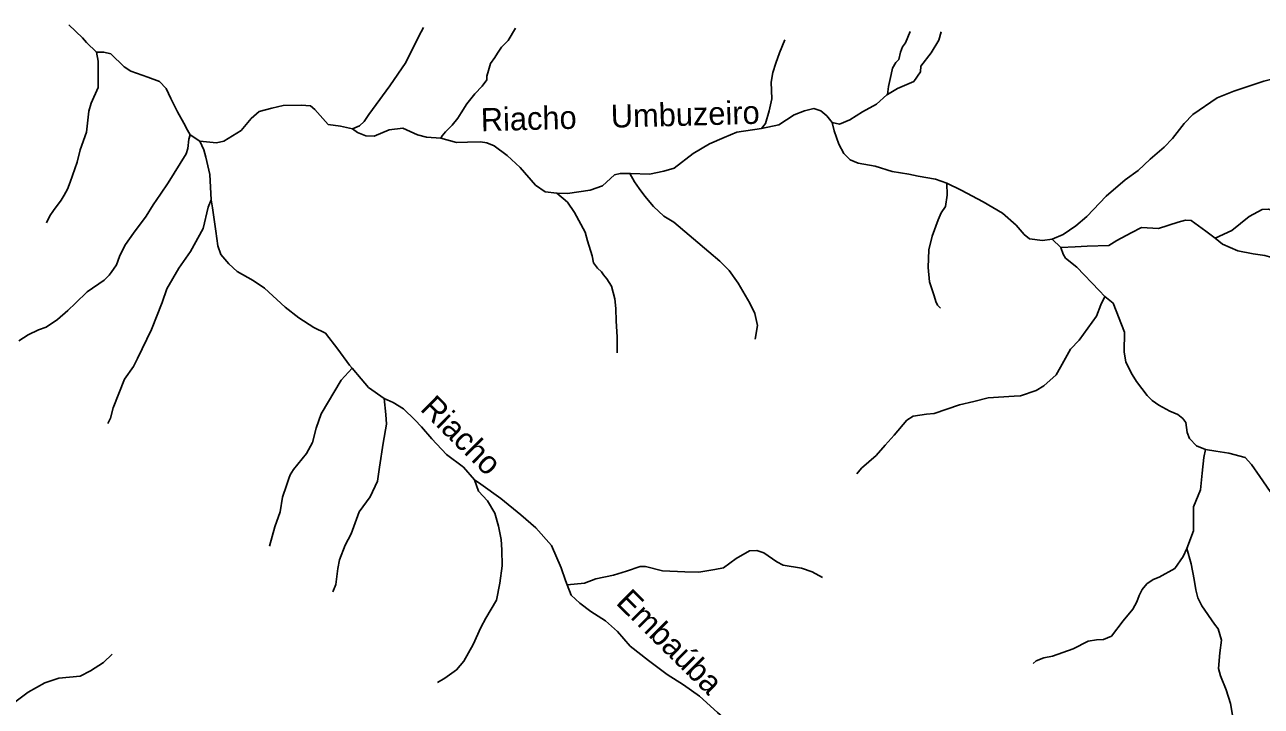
# Model space of a CAD drawing. Extents: x 717.8 to 772.7, y 8672.2 to 8728.
# Drawn here: x 745.36 to 756.1, y 8721.84 to 8727.76 of the extents above; entities that cross this region are included whole.
import ezdxf
from ezdxf.enums import TextEntityAlignment as Align

# ---------------------------------------------------------------- set-up
doc = ezdxf.new("R2010")
doc.units = 0
doc.header["$LTSCALE"] = 0.08
doc.linetypes.add('LONG_DASHED', pattern=[7.5, 6, -1.5])
doc.layers.add('61', color=7, linetype='Continuous')
doc.layers.add('9', color=7, linetype='LONG_DASHED', lineweight=25)

msp = doc.modelspace()

# ---------------------------------------------------------------- linework, layer by layer
at = {"layer": '9'}
for p, q in [((749.6275, 8727.726), (749.5623, 8727.6187)), ((746.8837, 8726.7438), (746.8014, 8726.7992))]:
    msp.add_line(p, q, dxfattribs=at)
for points in [[(745.7481, 8727.7567), (745.8668, 8727.6439), (745.9006, 8727.6014), (745.9877, 8727.5191)], [(748.2115, 8726.8523), (748.2708, 8726.8773), (748.3109, 8726.9155), (748.353, 8726.9771), (748.3841, 8727.0203), (748.5349, 8727.2265), (748.674, 8727.428), (748.7862, 8727.657), (748.8274, 8727.7327)], [(753.054, 8727.6982), (753.0136, 8727.5995), (752.9888, 8727.5648), (752.9694, 8727.5189), (752.9563, 8727.4546), (752.9305, 8727.4285), (752.9006, 8727.38), (752.888, 8727.3241), (752.8649, 8727.2194), (752.856, 8727.1491)], [(753.3221, 8727.696), (753.302, 8727.6217), (753.2353, 8727.5134), (753.1474, 8727.3962), (753.145, 8727.3471), (753.0863, 8727.2637), (752.943, 8727.2015), (752.856, 8727.1491)], [(749.5623, 8727.6187), (749.5033, 8727.5604), (749.4686, 8727.5108), (749.4454, 8727.4731), (749.4092, 8727.4186), (749.3912, 8727.3604), (749.3768, 8727.3095), (749.3779, 8727.2777), (749.3357, 8727.222), (749.2726, 8727.1573)], [(751.7637, 8726.8544), (751.7976, 8726.8975), (751.8307, 8727.0087), (751.8517, 8727.1129), (751.8467, 8727.2581), (751.8611, 8727.3417), (751.8862, 8727.4218), (751.9187, 8727.5127), (751.9652, 8727.6246)], [(745.5533, 8726.0352), (745.5817, 8726.0965), (745.6124, 8726.1432), (745.679, 8726.233), (745.7048, 8726.2754), (745.7343, 8726.3292), (745.7595, 8726.3877), (745.8181, 8726.5639), (745.8465, 8726.6701), (745.8996, 8726.8245), (745.9211, 8727.0067), (745.941, 8727.076), (746.0014, 8727.2108), (746.001, 8727.4398), (745.9877, 8727.5191)], [(746.8014, 8726.7992), (746.777, 8726.8397), (746.7445, 8726.9002), (746.6911, 8726.9991), (746.6312, 8727.1168), (746.5915, 8727.203), (746.5329, 8727.2635), (746.4322, 8727.302), (746.2862, 8727.353), (746.2262, 8727.3915), (746.1129, 8727.5028), (746.0497, 8727.5171), (745.9877, 8727.5191)], [(756.4406, 8727.3316), (756.3851, 8727.3307), (756.3369, 8727.3185), (756.1262, 8727.2669), (755.8644, 8727.1781), (755.7217, 8727.1203), (755.5081, 8726.9775), (755.4349, 8726.8991), (755.3341, 8726.7685), (755.2591, 8726.6938), (755.139, 8726.5879), (755.0338, 8726.4895), (754.923, 8726.4081), (754.7553, 8726.2679), (754.5882, 8726.0904), (754.4922, 8726.0084), (754.3818, 8725.9344), (754.2874, 8725.8947)], [(749.2726, 8727.1573), (749.2044, 8727.0683), (749.1541, 8726.991), (749.1258, 8726.9452), (749.0756, 8726.884), (749.017, 8726.8263), (748.9884, 8726.7917), (748.9771, 8726.7714)], [(752.856, 8727.1491), (752.8516, 8727.1464), (752.7618, 8727.0675), (752.6413, 8726.9996), (752.5314, 8726.9293), (752.4407, 8726.8922), (752.3758, 8726.9078)], [(748.2115, 8726.8523), (748.1062, 8726.8739), (747.9983, 8726.8905), (747.8846, 8727.0199), (747.8467, 8727.0528), (747.7644, 8727.0576), (747.6097, 8727.0563), (747.5101, 8727.032), (747.399, 8727.0016), (747.3301, 8726.9427), (747.2435, 8726.8366), (747.0929, 8726.7441), (747.0283, 8726.7296), (746.8837, 8726.7438)], [(752.3758, 8726.9078), (752.3313, 8726.9664), (752.2777, 8727.0077), (752.2179, 8727.029), (752.1376, 8727.0097), (752.046, 8726.973), (751.9142, 8726.8871), (751.7637, 8726.8544)], [(748.2115, 8726.8523), (748.2533, 8726.8202), (748.325, 8726.7901), (748.3997, 8726.7891), (748.5295, 8726.8442), (748.6464, 8726.8589), (748.7745, 8726.8009), (748.8545, 8726.7797), (748.9771, 8726.7714)], [(751.7637, 8726.8544), (751.5494, 8726.8219), (751.4373, 8726.7763), (751.3102, 8726.7206), (751.1705, 8726.6376), (751.0031, 8726.5112), (750.9142, 8726.4833), (750.7911, 8726.4594), (750.6249, 8726.465), (750.6181, 8726.465)], [(753.3735, 8726.3787), (753.2753, 8726.4137), (753.1234, 8726.4419), (753.0423, 8726.4577), (752.8966, 8726.4817), (752.7488, 8726.5271), (752.6016, 8726.5526), (752.5322, 8726.5821), (752.4772, 8726.6378), (752.436, 8726.7183), (752.3947, 8726.8357), (752.3758, 8726.9078)], [(745.3121, 8725.01), (745.3933, 8725.0627), (745.482, 8725.1048), (745.5492, 8725.1303), (745.6485, 8725.196), (745.7385, 8725.275), (745.804, 8725.3374), (745.9068, 8725.4362), (746.0537, 8725.5365), (746.0978, 8725.5807), (746.1141, 8725.6049), (746.16, 8725.6703), (746.1861, 8725.7435), (746.2136, 8725.7972), (746.2397, 8725.8464), (746.3083, 8725.9448), (746.4183, 8726.0939), (746.4801, 8726.1914), (746.5441, 8726.2831), (746.6082, 8726.384), (746.7661, 8726.6344), (746.7803, 8726.6811), (746.7885, 8726.7627), (746.8014, 8726.7992)], [(746.9835, 8726.2367), (746.9718, 8726.4563), (746.937, 8726.6053), (746.9205, 8726.6705), (746.8837, 8726.7438)], [(749.984, 8726.2946), (749.8833, 8726.305), (749.8005, 8726.3632), (749.6671, 8726.5156), (749.5533, 8726.6214), (749.442, 8726.7043), (749.3773, 8726.7314), (749.3222, 8726.7404), (749.2093, 8726.7374), (749.1126, 8726.7344), (748.9771, 8726.7714)], [(750.6181, 8726.465), (750.5351, 8726.4655), (750.4865, 8726.4524), (750.3827, 8726.3581), (750.2749, 8726.3202), (750.0783, 8726.2906), (749.984, 8726.2946)], [(751.7079, 8725.0243), (751.7268, 8725.1444), (751.7036, 8725.2491), (751.6621, 8725.337), (751.5609, 8725.5113), (751.4822, 8725.6221), (751.3997, 8725.7038), (751.3069, 8725.7839), (751.001, 8726.0417), (750.9158, 8726.0929), (750.8258, 8726.1761), (750.7506, 8726.2684), (750.6994, 8726.3326), (750.6605, 8726.3907), (750.6181, 8726.465)], [(753.3182, 8725.2935), (753.2907, 8725.3199), (753.277, 8725.3508), (753.2632, 8725.4024), (753.222, 8725.5227), (753.2106, 8725.6484), (753.216, 8725.8007), (753.2448, 8725.9204), (753.2961, 8726.0619), (753.3224, 8726.1224), (753.3608, 8726.1785), (753.3744, 8726.2753), (753.3735, 8726.3787)], [(754.2874, 8725.8947), (754.2048, 8725.8827), (754.0918, 8725.8955), (754.0448, 8725.9332), (753.9755, 8726.0161), (753.8564, 8726.1193), (753.6878, 8726.2176), (753.4984, 8726.3192), (753.3735, 8726.3787)], [(750.5086, 8724.905), (750.5094, 8725.0449), (750.4998, 8725.1808), (750.4971, 8725.2914), (750.4878, 8725.3739), (750.46, 8725.4839), (750.4208, 8725.5502), (750.392, 8725.583), (750.3736, 8725.6093), (750.3377, 8725.6421), (750.3049, 8725.6877), (750.2922, 8725.7477), (750.253, 8725.878), (750.2322, 8725.9531), (750.1395, 8726.1266), (750.0793, 8726.2148), (749.984, 8726.2946)], [(756.9762, 8726.3485), (756.8833, 8726.2784), (756.6995, 8726.2187), (756.6152, 8726.1826), (756.4684, 8726.1324), (756.2621, 8726.1268), (756.1651, 8726.153), (756.1115, 8726.1515), (755.9995, 8726.0901), (755.8472, 8725.968), (755.7044, 8725.9013)], [(746.0853, 8724.2932), (746.1095, 8724.3382), (746.1309, 8724.4271), (746.2307, 8724.6758), (746.3078, 8724.7884), (746.3437, 8724.8554), (746.4645, 8725.1088), (746.5581, 8725.3437), (746.5967, 8725.4616), (746.7022, 8725.6422), (746.8029, 8725.787), (746.9125, 8725.9848), (746.9581, 8726.1719), (746.9835, 8726.2367)], [(748.2083, 8724.7728), (748.1853, 8724.7984), (748.0831, 8724.9377), (747.9755, 8725.0773), (747.8749, 8725.1251), (747.7438, 8725.211), (747.6253, 8725.3014), (747.4473, 8725.4675), (747.3464, 8725.534), (747.2097, 8725.6112), (747.1351, 8725.6795), (747.0678, 8725.7597), (747.0421, 8725.8344), (747.0235, 8725.9627), (746.9957, 8726.1644), (746.9835, 8726.2367)], [(755.7044, 8725.9013), (755.6211, 8725.9632), (755.495, 8726.0569), (755.4457, 8726.0574), (755.381, 8726.0414), (755.2114, 8725.9848), (755.0649, 8725.9937), (754.9735, 8725.9478), (754.8482, 8725.8818), (754.7783, 8725.8382), (754.5905, 8725.8314), (754.4887, 8725.828), (754.3639, 8725.8203), (754.2874, 8725.8947)], [(756.6542, 8725.4873), (756.4013, 8725.6568), (756.3419, 8725.6824), (756.2368, 8725.7241), (756.1352, 8725.7512), (756.0337, 8725.7675), (755.9011, 8725.7913), (755.766, 8725.851), (755.7044, 8725.9013)], [(754.7442, 8725.3956), (754.6945, 8725.4471), (754.502, 8725.6507), (754.4021, 8725.7274), (754.3821, 8725.7642), (754.3639, 8725.8203)], [(752.5906, 8723.8542), (752.6318, 8723.9047), (752.7584, 8724.015), (752.8376, 8724.1036), (752.9145, 8724.1914), (753.0255, 8724.322), (753.0791, 8724.3546), (753.1956, 8724.3725), (753.264, 8724.3779), (753.4829, 8724.4549), (753.6082, 8724.483), (753.731, 8724.5155), (753.957, 8724.5292), (754.0138, 8724.5316), (754.1494, 8724.5783), (754.2139, 8724.6193), (754.3235, 8724.7149), (754.3599, 8724.7807), (754.4481, 8724.939), (754.5231, 8725.0158), (754.5589, 8725.0693), (754.6731, 8725.2247), (754.7114, 8725.3227), (754.7442, 8725.3956)], [(755.6195, 8724.0675), (755.5409, 8724.098), (755.4803, 8724.1624), (755.4611, 8724.2149), (755.448, 8724.3019), (755.4235, 8724.3356), (755.3788, 8724.3708), (755.3094, 8724.3986), (755.2139, 8724.4515), (755.1564, 8724.4911), (755.1121, 8724.5354), (755.0189, 8724.6558), (754.9824, 8724.7178), (754.9288, 8724.8258), (754.9125, 8724.9144), (754.915, 8725.0866), (754.8174, 8725.3385), (754.7442, 8725.3956)], [(747.4903, 8723.226), (747.5364, 8723.3936), (747.5818, 8723.5247), (747.603, 8723.6528), (747.638, 8723.7535), (747.6567, 8723.8134), (747.6696, 8723.8452), (747.6977, 8723.893), (747.8121, 8724.0316), (747.8621, 8724.1271), (747.8945, 8724.2517), (747.9373, 8724.3757), (748.1124, 8724.6698), (748.2083, 8724.7728)], [(748.4867, 8724.5098), (748.3494, 8724.604), (748.2854, 8724.6787), (748.2083, 8724.7728)], [(748.0405, 8722.8281), (748.0657, 8722.894), (748.0833, 8723.0333), (748.0987, 8723.1069), (748.148, 8723.2353), (748.1996, 8723.3341), (748.2698, 8723.524), (748.3641, 8723.6558), (748.4278, 8723.7919), (748.4453, 8723.9126), (748.476, 8724.12), (748.5045, 8724.2868), (748.5012, 8724.3692), (748.4867, 8724.5098)], [(749.2694, 8723.8025), (749.1759, 8723.9115), (749.0267, 8724.0224), (748.8994, 8724.1574), (748.8094, 8724.2627), (748.7524, 8724.3253), (748.6548, 8724.4207), (748.5637, 8724.4734), (748.4867, 8724.5098)], [(755.4579, 8723.2047), (755.5157, 8723.3582), (755.5164, 8723.5694), (755.5749, 8723.7163), (755.5908, 8723.8594), (755.6061, 8723.9954), (755.6195, 8724.0675)], [(756.3163, 8723.5385), (756.1824, 8723.7026), (756.09, 8723.8301), (756.0192, 8723.9359), (755.9633, 8723.9978), (755.8208, 8724.0337), (755.7087, 8724.0529), (755.6195, 8724.0675)], [(748.9477, 8722.0432), (749.012, 8722.0798), (749.1129, 8722.1529), (749.1772, 8722.2261), (749.2598, 8722.3725), (749.3241, 8722.519), (749.37, 8722.6013), (749.4615, 8722.7577), (749.4893, 8722.9034), (749.5115, 8723.0549), (749.5073, 8723.1955), (749.503, 8723.2829), (749.4796, 8723.399), (749.4455, 8723.513), (749.3825, 8723.6192), (749.304, 8723.7043), (749.2694, 8723.8025)], [(750.0747, 8722.8912), (750.061, 8722.9281), (750.0216, 8723.0379), (749.9402, 8723.2318), (749.8033, 8723.3862), (749.6737, 8723.4976), (749.4977, 8723.6409), (749.326, 8723.7652), (749.2694, 8723.8025)], [(752.2923, 8722.9529), (752.2039, 8723.004), (752.1097, 8723.0345), (751.9515, 8723.062), (751.8959, 8723.0904), (751.7827, 8723.1687), (751.7217, 8723.1878), (751.6593, 8723.1849), (751.5437, 8723.1181), (751.4321, 8723.0366), (751.358, 8723.0231), (751.2184, 8723.0001), (751.0958, 8723.0033), (750.9031, 8723.0126), (750.7563, 8723.0492), (750.7103, 8723.0492), (750.5903, 8723.0081), (750.4761, 8722.9739), (750.323, 8722.9421), (750.2252, 8722.9056), (750.0747, 8722.8912)], [(754.1218, 8722.2079), (754.15, 8722.2312), (754.2161, 8722.2548), (754.2904, 8722.27), (754.4702, 8722.3348), (754.5998, 8722.4004), (754.6728, 8722.4133), (754.7325, 8722.4167), (754.8041, 8722.4457), (754.9046, 8722.5761), (754.9881, 8722.6784), (755.0222, 8722.7432), (755.0418, 8722.7987), (755.0699, 8722.8507), (755.1108, 8722.9001), (755.1661, 8722.9354), (755.2172, 8722.9565), (755.3527, 8723.0331), (755.4255, 8723.1365), (755.4579, 8723.2047)], [(755.9085, 8721.4291), (755.8808, 8721.562), (755.8533, 8721.6662), (755.8538, 8721.7586), (755.8357, 8721.8593), (755.7991, 8721.9783), (755.7491, 8722.101), (755.7315, 8722.1641), (755.7427, 8722.3001), (755.7579, 8722.4088), (755.7283, 8722.5079), (755.6979, 8722.5487), (755.5864, 8722.7074), (755.5532, 8722.7782), (755.5344, 8722.8464), (755.5216, 8722.9368), (755.4944, 8723.0723), (755.4579, 8723.2047)], [(751.9137, 8721.3301), (751.808, 8721.4281), (751.6443, 8721.5671), (751.5113, 8721.6684), (751.3817, 8721.7804), (751.225, 8721.9241), (751.0848, 8722.0219), (750.9435, 8722.1126), (750.7822, 8722.2316), (750.6232, 8722.3565), (750.5133, 8722.4849), (750.4066, 8722.5769), (750.2794, 8722.6594), (750.184, 8722.7301), (750.1089, 8722.8014), (750.0747, 8722.8912)], [(746.124, 8722.2868), (746.0491, 8722.2161), (745.9355, 8722.1432), (745.8442, 8722.0964), (745.6584, 8722.0798), (745.5382, 8722.0381), (745.3923, 8721.9573), (745.278, 8721.8707), (745.2138, 8721.8353), (745.1248, 8721.7469), (745.0681, 8721.6093), (745.0438, 8721.5121), (744.979, 8721.3745), (744.8899, 8721.245), (744.7716, 8721.1422), (744.6195, 8721.0435)]]:
    msp.add_lwpolyline(points, dxfattribs=at)

# ---------------------------------------------------------------- texts
at = {"layer": '61'}
for s, rotation, p in [('Riacho    Umbuzeiro', 1.56, (750.5383, 8726.8638)), ('Riacho                     Embaúba', 315.276, (750.0471, 8723.1677))]:
    msp.add_text(s, height=0.2, rotation=rotation, dxfattribs=at).set_placement(p, align=Align.CENTER)

doc.saveas('drawing.dxf')
